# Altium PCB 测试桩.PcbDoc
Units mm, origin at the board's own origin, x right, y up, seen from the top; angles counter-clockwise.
Board outline 97.4 x 53.11 mm, 4 copper layers (Top Layer, Internal Plane 1, Internal Plane 2, Bottom Layer); 73 components, 53 nets, 362 pads, 111 vias.
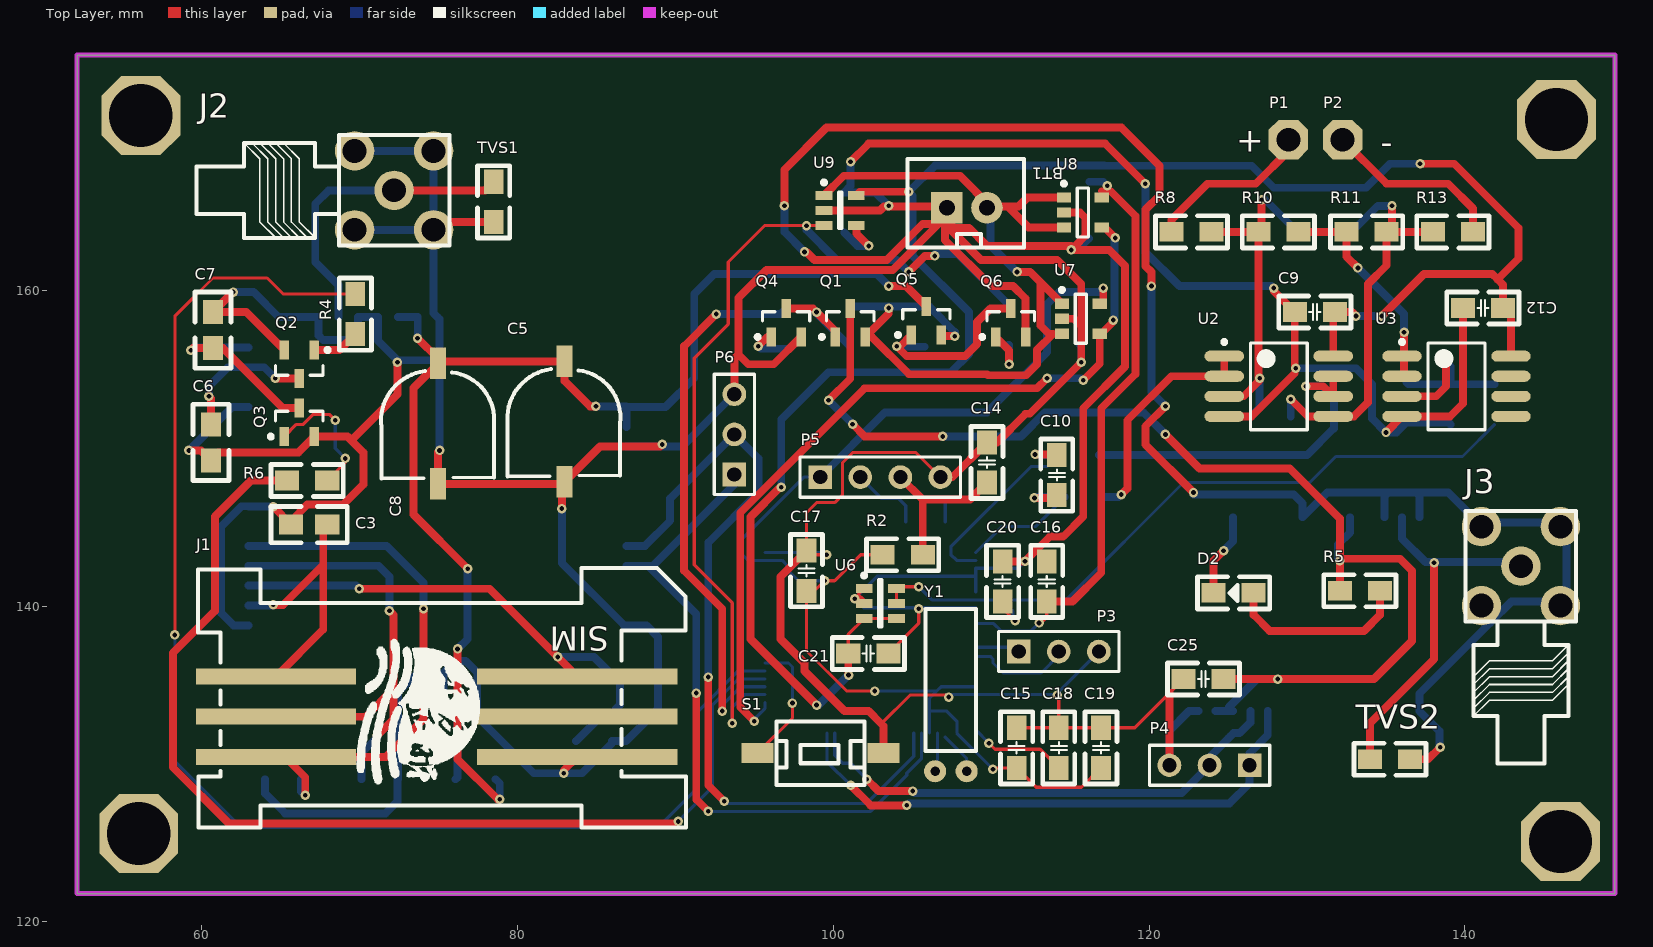
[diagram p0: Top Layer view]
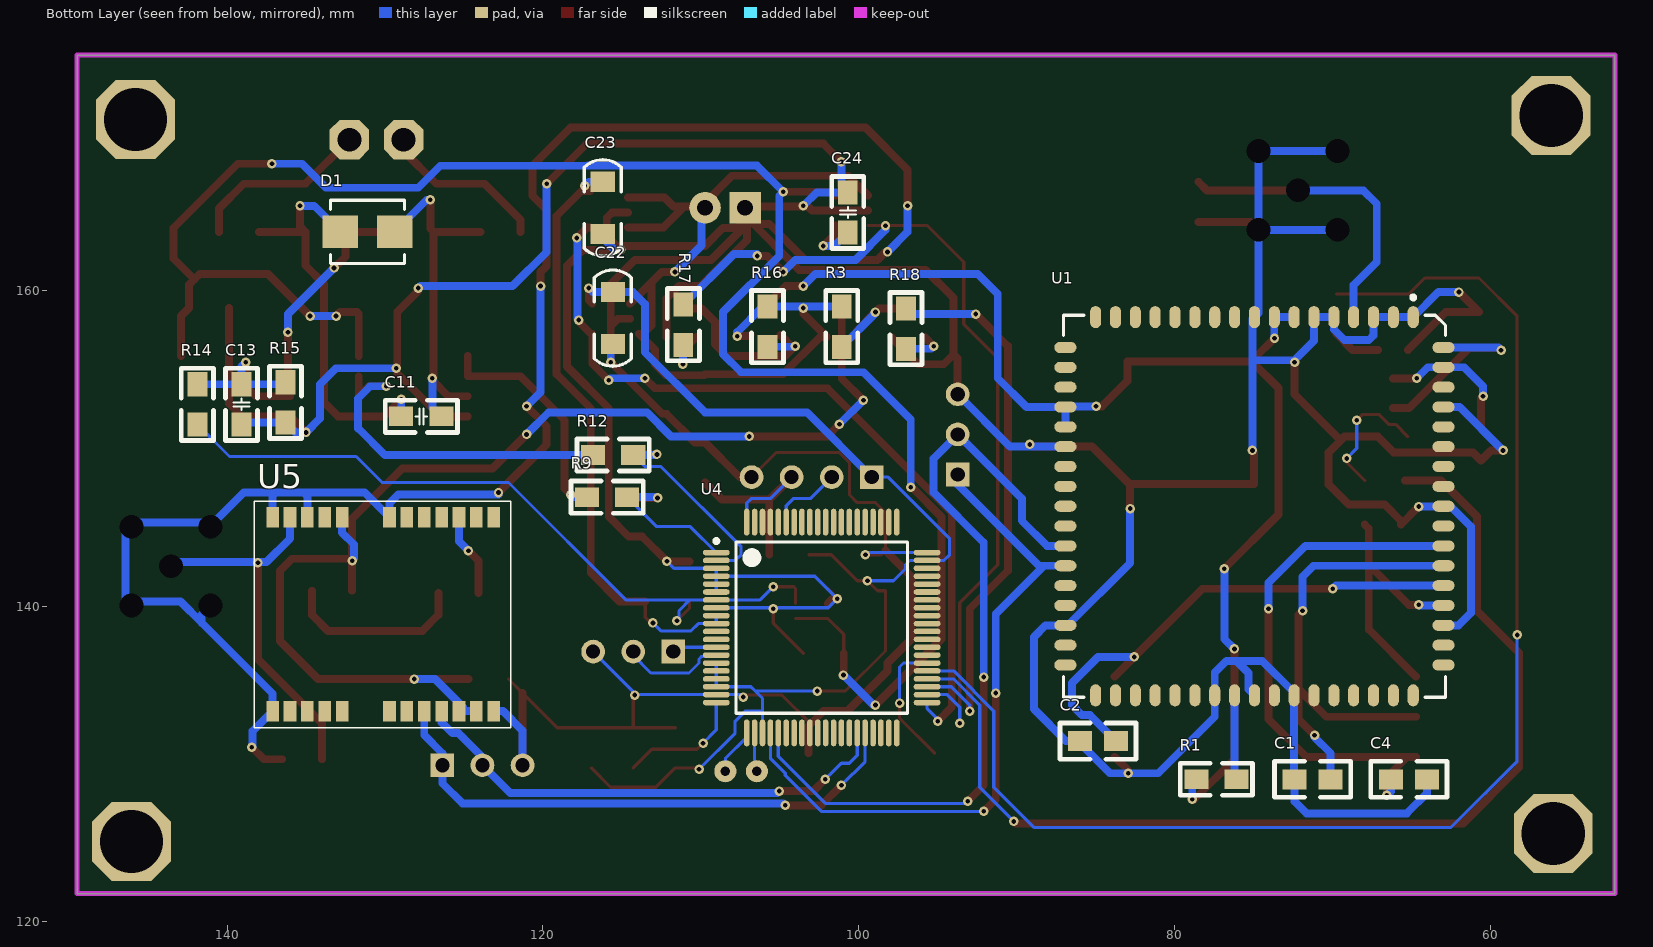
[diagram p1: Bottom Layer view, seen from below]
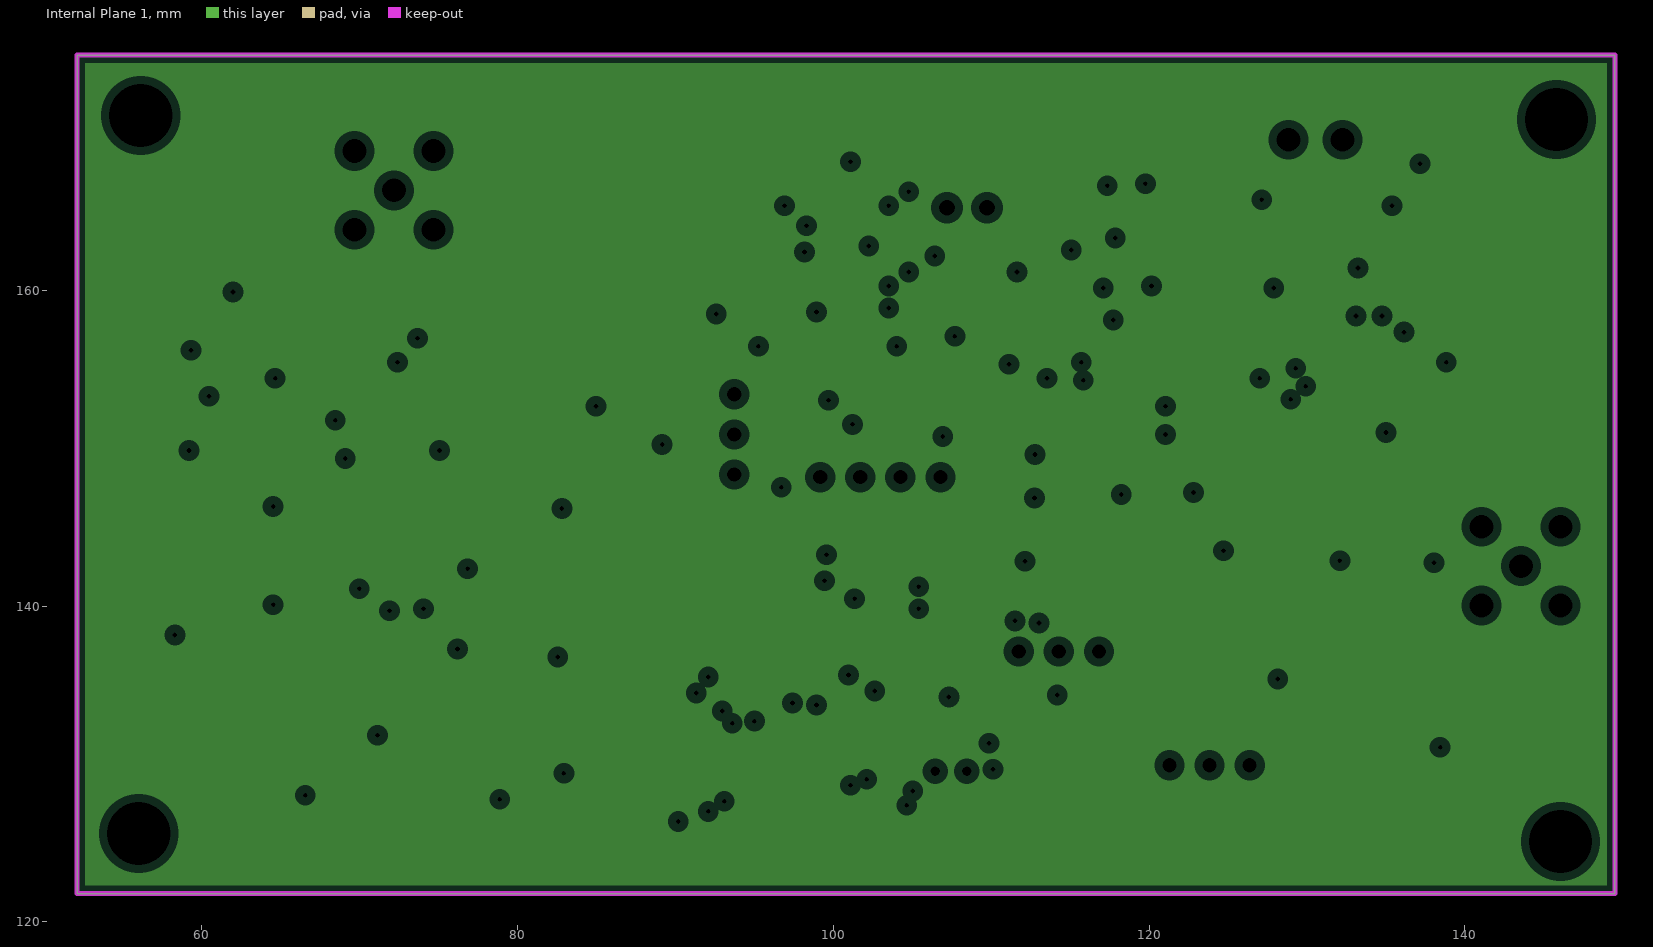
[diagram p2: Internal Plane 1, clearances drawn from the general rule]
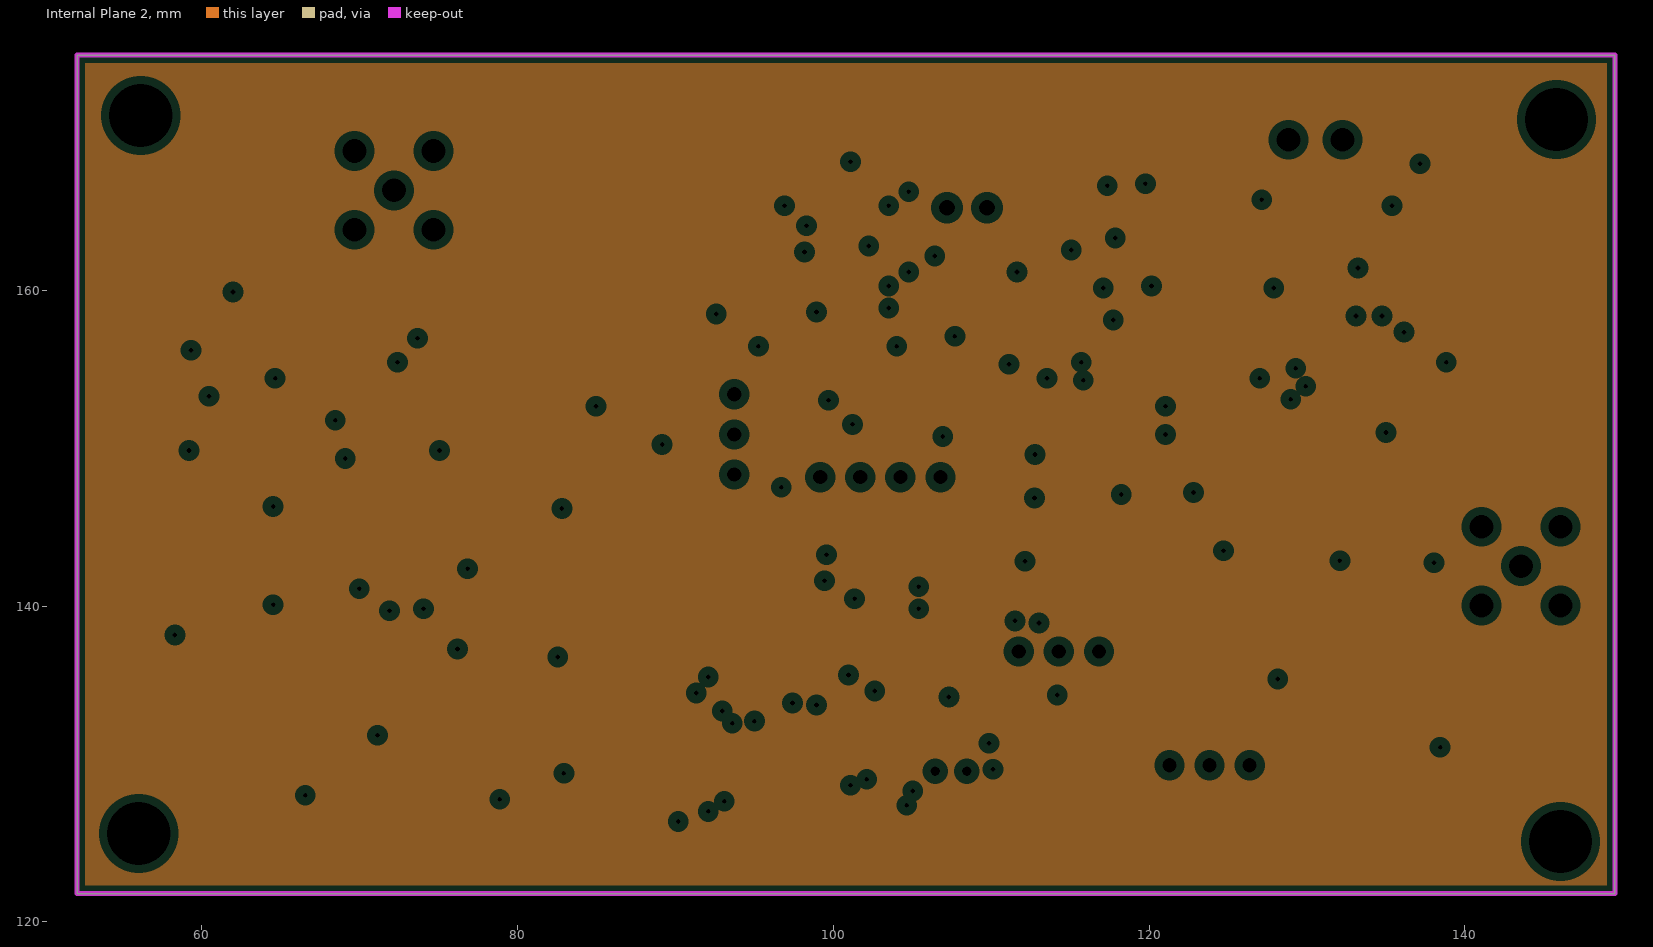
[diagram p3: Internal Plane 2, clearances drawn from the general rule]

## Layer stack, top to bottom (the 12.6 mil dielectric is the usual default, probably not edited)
Top Layer: signal copper 0.0356
Dielectric: dielectric 0.32, FR-4, Dk 4.8
Internal Plane 1: plane copper 0.0356
Dielectric: dielectric 0.32, FR-4, Dk 4.8
Internal Plane 2: plane copper 0.0356
Dielectric: dielectric 0.32, FR-4, Dk 4.8
Bottom Layer: signal copper 0.0356

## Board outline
52.1,121.793 52.1,174.9 149.5,174.9 149.5,121.793

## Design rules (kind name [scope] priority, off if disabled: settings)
Clearance Ploygon_Clearance [InPolygon] p1: gap=0.5
Clearance [All] p2: gap=0.15
PlaneClearance [All] p1: clearance=0.508
PlaneConnect [All] p1: planeconnectstyle=Relief reliefexpansion=0.508 reliefentries=4 reliefconductorwidth=0.254 reliefairgap=0.254
PolygonConnect [All] p1: connectstyle=Relief reliefconductorwidth=0.254 reliefentries=4 polygonreliefangle="90 Angle" airgapwidth=0.254
RoutingVias [All] p1: holewidth=0.3 width=0.6 viastyle="Through Hole" minholewidth=0.3 minwidth=0.6 maxholewidth=0.3 maxwidth=0.6
SolderMaskExpansion [All] p1: expansion=0.102
Width [All] p1: maxlimit=2 minlimit=0.2 preferedwidth=0.2 minimp=50.000000 maximp=50.000000 favimp=50.000000
26 further rules are at their usual default settings.

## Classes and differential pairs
component class U_GPRS模块: C1 C2 C3 C4 C5 C6 C7 C8 J1 J2 Q2 Q3 R1 R4 R6 TVS1 U1
component class U_GPS模块: C25 D2 J3 R5 TVS2 U5
component class U_信号调理: C9 C10 C11 C12 C13 D1 P1 P2 R8 R9 R10 R11 R12 R13 R14 R15 U2 U3
component class U_核心板: C14 C15 C16 C17 C18 C19 C20 C21 P3 P4 P5 P6 R2 S1 U4 U6 Y1
component class U_电源管理: BT1 C22 C23 C24 Q1 Q4 Q5 Q6 R3 R16 R17 R18 U7 U8 U9

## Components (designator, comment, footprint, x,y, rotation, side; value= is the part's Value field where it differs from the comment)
BT1 "" XH2.54-2P 107.188,165.227 r0 top
C1 "Cap" 0805 70.104,129.032 r0 bottom
C2 "Cap" 0805 83.693,131.445 r0 bottom
C3 "Cap" 0805 67.945,145.161 r180 top
C4 "Cap" 0805 66.294,129.032 r180 bottom
C5 "16V" 铝电解电容 82.931,155.067 r270 top
C6 "Cap" 0805 60.579,151.511 r270 top
C7 "Cap" 0805 60.706,156.337 r90 top
C8 "16V" 铝电解电容 74.93,154.94 r270 top
C9 "" 0805C 131.765,158.623 r180 top
C10 "Cap" 0805C 114.15,147.026 r90 top
C11 "" 0805C 128.971,152.019 r180 bottom
C12 "" 0805C 142.411,158.877 r180 top
C13 "" 0805C 139.087,151.511 r90 bottom
C14 "" 0805C 109.728,150.368 r270 top
C15 "" 0805C 111.61,129.754 r90 top
C16 "" 0805C 113.515,140.295 r90 top
C17 "" 0805C 98.298,140.97 r90 top
C18 "" 0805C 114.277,129.754 r90 top
C19 "" 0805C 116.944,129.754 r90 top
C20 "" 0805C 110.721,142.835 r270 top
C21 "" 0805C 103.482,136.993 r180 top
C22 "" 1206C 115.57,159.893 r270 bottom
C23 "" 1206C 116.205,166.878 r270 bottom
C24 "" 0805C 100.688,166.203 r270 bottom
C25 "Cap" 0805C 124.714,135.382 r180 top
D1 "SMCJ6.5CA" DO-214AA 131.108,163.703 r180 bottom
D2 "" 0805D 125.349,140.843 r180 top
J1 "SIM" SIM-6 72.898,134.239 r180 top
J2 "*" SM_ANT 74.676,163.83 r180 top
J3 "Antenna" SM_ANT 146.05,145.034 r270 top
P1 "Plug" PZ1 128.822,169.545 r180 top
P2 "Plug" PZ1 132.251,169.545 r180 top
P3 "Header 3" HDR1X3 111.737,137.12 r0 top
P4 "Header 3" HDR1X3 126.365,129.921 r180 top
P5 "Header 4" HDR1X4 99.164,148.169 r0 top
P6 "Header 3" HDR1X3 93.726,148.336 r90 top
Q1 "IRLML6401TRPBF" SOT23-3 101.069,157.948 r90 top
Q2 "NPN" SOT23-3 66.167,155.321 r270 top
Q3 "NPN" SOT23-3 66.167,151.638 r90 top
Q4 "8050" SOT23-3 97.005,157.948 r90 top
Q5 "IRLML6401TRPBF" SOT23-3 105.895,158.075 r90 top
Q6 "8050" SOT23-3 111.229,157.948 r90 top
R1 "Res2" 0805r 76.073,129.032 r0 bottom
R2 "" 0805R 103.124,143.256 r0 top
R3 "" 0805R 101.069,158.964 r270 bottom
R4 "Res2" 0805r 69.723,159.766 r270 top
R5 "Res2" 0805R 134.62,140.97 r180 top
R6 "Res2" 0805r 65.405,147.955 r0 top
R8 "" 0805R 121.412,163.703 r0 top
R9 "" 0805R 117.198,146.899 r180 bottom
R10 "" 0805R 126.917,163.703 r0 top
R11 "" 0805R 132.505,163.703 r0 top
R12 "" 0805R 116.817,149.566 r180 bottom
R13 "" 0805R 137.966,163.703 r0 top
R14 "" 0805R 141.881,151.511 r90 bottom
R15 "" 0805R 136.293,154.178 r270 bottom
R16 "" 0805R 105.768,158.964 r270 bottom
R17 "" 0805R 111.102,159.091 r270 bottom
R18 "" 0805R 97.005,158.837 r270 bottom
S1 "SW-PB" SW-KEY 99.187,130.683 r0 top
TVS1 "Res2" 0805r 78.486,164.338 r90 top
TVS2 "Res2" 0805r 136.525,130.302 r180 top
U1 "MG323-B" MG323-b 74.93,146.327 r270 bottom
U2 "OPA2335" SOP-8 128.209,153.924 r0 top
U3 "LM358" SOP-8 139.468,153.924 r0 top
U4 "MSP430F6720IPNR" QFP-80 102.339,138.644 r180 bottom
U5 "NEO-7M-0-000" NEO-7 132.715,133.35 r270 bottom
U6 "REF3212" SOT23-6 102.974,140.168 r0 top
U7 "TPS780330220" SOT23-5 115.674,158.202 r0 top
U8 "TPS780330220" SOT23-5 115.801,164.933 r0 top
U9 "TPS71733DCKR" SC70-5 100.434,165.06 r0 top
Y1 "XTAL" XTAL2 107.442,129.54 r0 top

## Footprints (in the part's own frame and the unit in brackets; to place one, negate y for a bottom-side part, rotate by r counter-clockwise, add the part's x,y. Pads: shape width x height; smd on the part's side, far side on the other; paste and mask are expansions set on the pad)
0805 [mil]
  rect 60x50 smd: 1(0,0) 2(90,0)
  silkscreen extent -50,-45 140,45
0805C [mm]
  rect 1.524x1.25 smd: 1(0,0) 2(2.54,0)
  silkscreen extent -1.02,-1.02 3.56,1.02
0805D [mm]
  rect 1.524x1.25 smd: 1(-1.27,0) 2(1.27,0)
  silkscreen extent -2.29,-1.02 2.29,1.02
0805r [mm]
  rect 1.524x1.25 smd: 1(0,0) 2(2.54,0)
  silkscreen extent -1.02,-1.02 3.56,1.02
0805R [mm]
  rect 1.524x1.25 smd: 1(0,0) 2(2.54,0)
  silkscreen extent -1.02,-1.02 3.56,1.02
1206C [mil]
  rect 50x60 smd: 1(0,0) 2(130,0)
  silkscreen extent -55,-46 185,46
DO-214AA [mm] "DO-214AA"
  rect 2.25x2.05 smd: 1(-1.725,0) 2(1.725,0)
  silkscreen extent -2.35,-2 2.35,2, body extent -2.35,-1.97 2.35,1.97, height 2.44
HDR1X3 [mm] "Connector; Header; 3 Position"
  rect 1.5x1.5 hole 0.9: 1(0,0)
  round 1.5 hole 0.9: 2(2.54,0) 3(5.08,0)
  silkscreen extent -1.27,-1.27 6.35,1.27
HDR1X4 [mm] "Connector; Header; 4 Position"
  rect 1.5x1.5 hole 0.9: 1(0,0)
  round 1.5 hole 0.9: 2(2.54,0) 3(5.08,0) 4(7.62,0)
  silkscreen extent -1.27,-1.27 8.89,1.27
MG323-b [mm] "LCC, 68-Pins, Body 24.2x24.2mm (max), Pitch 1.26mm, IPC Medium Density"
  oval 1.4x0.7 smd: 1(-11.975,10.056) 2(-11.975,8.799) 3(-11.975,7.542) 4(-11.975,6.285) 5(-11.975,5.028) 6(-11.975,3.771) 7(-11.975,2.514) 8(-11.975,1.257) 9(-11.975,0) 10(-11.975,-1.257) 11(-11.975,-2.514) 12(-11.975,-3.771) 13(-11.975,-5.028) 14(-11.975,-6.285) 15(-11.975,-7.542) 16(-11.975,-8.799) 17(-11.975,-10.056) 35(11.975,-10.056) 36(11.975,-8.799) 37(11.975,-7.542) 38(11.975,-6.285) 39(11.975,-5.028) 40(11.975,-3.771) 41(11.975,-2.514) 42(11.975,-1.257) 43(11.975,0) 44(11.975,1.257) 45(11.975,2.514) 46(11.975,3.771) 47(11.975,5.028) 48(11.975,6.285) 49(11.975,7.542) 50(11.975,8.799) 51(11.975,10.056)
  oval 0.7x1.4 smd: 18(-10.056,-11.975) 19(-8.799,-11.975) 20(-7.542,-11.975) 21(-6.285,-11.975) 22(-5.028,-11.975) 23(-3.771,-11.975) 24(-2.514,-11.975) 25(-1.257,-11.975) 26(0,-11.975) 27(1.257,-11.975) 28(2.514,-11.975) 29(3.771,-11.975) 30(5.028,-11.975) 31(6.285,-11.975) 32(7.542,-11.975) 33(8.799,-11.975) 34(10.056,-11.975) 52(10.056,11.975) 53(8.799,11.975) 54(7.542,11.975) 55(6.285,11.975) 56(5.028,11.975) 57(3.771,11.975) 58(2.514,11.975) 59(1.257,11.975) 60(0,11.975) 61(-1.257,11.975) 62(-2.514,11.975) 63(-3.771,11.975) 64(-5.028,11.975) 65(-6.285,11.975) 66(-7.542,11.975) 67(-8.799,11.975) 68(-10.056,11.975)
  silkscreen extent -13.35,-12.1 12.1,12.1, body extent -12.13,-12.13 11.87,11.87, height 3.02
NEO-7 [mm] "GPS模块"
  rect 1.3x0.8 smd: 1(-12.28,9.6) 2(-12.28,8.5) 3(-12.28,7.4) 4(-12.28,6.3) 5(-12.28,5.2) 6(-12.28,4.1) 7(-12.28,3) 8(-12.28,0) 8(-12.28,0) 9(-12.28,-1.1) 10(-12.28,-2.2) 11(-12.28,-3.3) 12(-12.28,-4.4) 13(0,-4.4) 13(0,-4.4) 14(0,-3.3) 15(0,-2.2) 16(0,-1.1) 17(0,0) 18(0,3) 19(0,4.1) 20(0,5.2) 21(0,6.3) 22(0,7.4) 23(0,8.5) 24(0,9.6)
  silkscreen extent -13.3,-5.56 1.04,10.67
PZ1 [mm]
  oct 2.5x2.5 hole 1.5: 1(0,0)
QFP-80 [mm]
  oval 1.7x0.35 smd: 1(-6.675,4.75) 2(-6.675,4.25) 3(-6.675,3.75) 4(-6.675,3.25) 5(-6.675,2.75) 6(-6.675,2.25) 7(-6.675,1.75) 8(-6.675,1.25) 9(-6.675,0.75) 10(-6.675,0.25) 11(-6.675,-0.25) 12(-6.675,-0.75) 13(-6.675,-1.25) 14(-6.675,-1.75) 15(-6.675,-2.25) 16(-6.675,-2.75) 17(-6.675,-3.25) 18(-6.675,-3.75) 19(-6.675,-4.25) 20(-6.675,-4.75) 41(6.675,-4.75) 42(6.675,-4.25) 43(6.675,-3.75) 44(6.675,-3.25) 45(6.675,-2.75) 46(6.675,-2.25) 47(6.675,-1.75) 48(6.675,-1.25) 49(6.675,-0.75) 50(6.675,-0.25) 51(6.675,0.25) 52(6.675,0.75) 53(6.675,1.25) 54(6.675,1.75) 55(6.675,2.25) 56(6.675,2.75) 57(6.675,3.25) 58(6.675,3.75) 59(6.675,4.25) 60(6.675,4.75)
  oval 0.35x1.7 smd: 21(-4.75,-6.675) 22(-4.25,-6.675) 23(-3.75,-6.675) 24(-3.25,-6.675) 25(-2.75,-6.675) 26(-2.25,-6.675) 27(-1.75,-6.675) 28(-1.25,-6.675) 29(-0.75,-6.675) 30(-0.25,-6.675) 31(0.25,-6.675) 32(0.75,-6.675) 33(1.25,-6.675) 34(1.75,-6.675) 35(2.25,-6.675) 36(2.75,-6.675) 37(3.25,-6.675) 38(3.75,-6.675) 39(4.25,-6.675) 40(4.75,-6.675) 61(4.75,6.675) 62(4.25,6.675) 63(3.75,6.675) 64(3.25,6.675) 65(2.75,6.675) 66(2.25,6.675) 67(1.75,6.675) 68(1.25,6.675) 69(0.75,6.675) 70(0.25,6.675) 71(-0.25,6.675) 72(-0.75,6.675) 73(-1.25,6.675) 74(-1.75,6.675) 75(-2.25,6.675) 76(-2.75,6.675) 77(-3.25,6.675) 78(-3.75,6.675) 79(-4.25,6.675) 80(-4.75,6.675)
  silkscreen extent -6.8,-5.43 5.43,5.6, body extent -4.75,-4.75 4.75,4.75, height 2.45
SC70-5 [mm] "SOT23, 5-Leads, Body 2.03x2.45mm, Pitch 0.95mm, IPC Medium Density"
  rect 1.05x0.55 smd: 1(-1.025,0.95) 2(-1.025,0) 3(-1.025,-0.95) 4(1.025,-0.95) 5(1.025,0.95)
  silkscreen extent -1.15,-1.15 0.1,1.9, body extent -0.67,-1.12 0.67,1.13, height 1.1
SIM-6 [mil]
  rect 400x40 smd: 1(322.79,149) 2(322.79,49) 3(322.79,-51)
  rect 500x40 smd: 4(-428.78,-51) 5(-428.78,49) 6(-428.78,149)
  silkscreen extent -700,-322 518,326, body extent -676,-341 490,336, height 102
SM_ANT [mm]
  round 2.5 / inner round 0 / far side round 0 hole 1.5: 1(2.5,-2.5) 2(0,0) 2(0,-5) 2(5,0) 2(5,-5)
  silkscreen extent -1,-6 15,1, body extent -1.07,-6.1 14.03,0.9, height 9.86
SOP-8 [mm]
  oval 2.5x0.7 smd: 1(-3.45,1.905) 2(-3.45,0.635) 3(-3.45,-0.635) 4(-3.45,-1.905) 5(3.45,-1.905) 6(3.45,-0.635) 7(3.45,0.635) 8(3.45,1.905)
  silkscreen extent -3.57,-2.75 1.8,2.93, body extent -2.73,-2.75 2.73,2.75, height 2.03
SOT23-3 [mm] "SOT23, 3-Leads, Body 2.9x1.3mm, Pitch 0.95mm, Lead Span 2.5mm, IPC High Density"
  rect 1.2x0.6 smd: 1(-0.9,0.95) 2(-0.9,-0.95) 3(0.9,0)
  silkscreen extent -1.02,-1.5 0.7,1.92, body extent -0.7,-1.5 0.7,1.5, height 1.1
SOT23-5 [mm] "SOT23, 5-Leads, Body 2.9x1.6mm, Pitch 0.95mm, Lead Span 2.8mm, IPC High Density"
  rect 0.9x0.65 smd: 1(-1.2,0.95) 2(-1.2,0) 3(-1.2,-0.95) 4(1.2,-0.95) 5(1.2,0.95)
  silkscreen extent -1.32,-1.55 0.35,1.95, body extent -0.9,-1.55 0.9,1.55, height 1.45
SOT23-6 [mm] "SOT23, 6-Leads, Body 2.90x2.45mm, Pitch 0.95mm, IPC Medium Density"
  rect 1.05x0.55 smd: 1(-1.025,0.95) 2(-1.025,0) 3(-1.025,-0.95) 4(1.025,-0.95) 5(1.025,0) 6(1.025,0.95)
  silkscreen extent -1.15,-1.5 0.1,1.9, body extent -1.4,-1.45 1.4,1.45, height 1.45
SW-KEY [mm]
  rect 2.032x1.27 smd: 1(-4,0) 2(4,0)
  silkscreen extent -2.8,-2 2.8,2
XH2.54-2P [mm] "脚间距2.54的防呆插座"
  rect 2x2 hole 1: 1(0,0)
  round 2 hole 1: 2(2.54,0)
  silkscreen extent -2.5,-2.5 4.9,3.1
XTAL2 [mm] "3.2 X 9"
  round 1.4 hole 0.6: 1(-1,0) 2(1,0)
  silkscreen extent -1.6,1.27 1.6,10.27
铝电解电容 [mm]
  rect 2x1 smd: 1(-0.43,0.037) 2(7.199,0.037)
  silkscreen extent 0.06,-3.59 6.84,3.59

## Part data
BT1: library part "Header 2", "Header, 2-Pin"
C1 C2 C3 C4 C6 C7: "Capacitor"
C5 C8: library part "Cap Pol2", "贴片铝电解电容"
C9 C11 C12 C13 C20 C21 C24: library part Cap, "瓷片电容"
C10 C25: "贴片电容"
C14 C15 C16 C17 C18 C19: library part Cap, "贴片电容"
C22 C23: library part "Cap Pol1", "钽电容"
D1: library part DIODE_TVS, "双向TVS二极管 5V耐压"
D2: library part LED2, "贴片红色发光管"
J1: library part CON6, "Connector"
J2: library part C, "Connector"
J3: "天线"
P3 P4 P6: "Header, 3-Pin"
P5: "Header, 4-Pin"
Q1 Q5: "小功率MOSFET"
Q2 Q3 Q4 Q6: library part NPN_SOT, "NPN型贴片三极管"
R1 R4 R6 TVS1 TVS2: "Resistor"
R2 R8 R9 R10 R11 R12 R13 R14 R15: library part Res2, "贴片电阻"
R3 R16 R17 R18: library part Res2, "碳膜电阻"
R5: "贴片碳膜电阻"
S1: "Switch"
U2: "自归零CMOS运放"
U3: "运算放大器"
U4: library part MSP430F6720, "MSP430处理器80引脚封装"
U5: library part NEO-7, "U-Blox GPRS模块"
U6: "串联基准"
U7 U8: library part TPS780220330, "线性稳压器"
U9: library part TPS71701, "高PSRR线性稳压器"
Y1: "无源晶振"

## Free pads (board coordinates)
  oct 5x5 hole 4: 0(56.007,125.603) 0(56.134,171.069) 0(145.796,170.815) 0(146.05,125.095)

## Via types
v1: diameter 0.6, hole 0.3, Top Layer to Bottom Layer, 111 vias

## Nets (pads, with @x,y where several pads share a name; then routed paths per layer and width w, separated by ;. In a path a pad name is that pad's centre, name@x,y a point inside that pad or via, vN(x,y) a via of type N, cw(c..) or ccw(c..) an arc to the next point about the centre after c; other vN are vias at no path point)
+1.25V: C20.2 R14.1 U4.7 U6.5 U6.6 | length 47
  Top Layer w0.2: U6.5 U6.6 104.104,141.224 v1(105.41,141.224) ; C20.2 110.721,139.85 v1(111.506,139.065)
  Bottom Layer w0.2: v1(105.41,141.224) 106.24,140.394 U4.7 110.685,140.394 ; v1(111.506,139.065) 111.379,139.192 111.379,139.7 110.685,140.394 ; R14.1 139.849,149.479 131.826,149.479 130.175,147.828 122.174,147.828 114.74,140.394 110.685,140.394
ANALOG_OUTPUT_N: C10.2 R12.2 U4.2 | length 14.4
  Top Layer w0.5: v1(112.776,149.606) 114.11,149.606 C10.2
  Bottom Layer w0.2: U4.2 107.804,142.894 107.442,143.256 107.442,143.764 112.522,148.844 113.554,148.844 R12.2
  Bottom Layer w0.5: v1(112.776,149.606) 112.816,149.566 R12.2
ANALOG_OUTPUT_P: C10.1 R9.2 U4.1 | length 10.6
  Top Layer w0.5: v1(112.736,146.852) 113.975,146.852 C10.1
  Bottom Layer w0.2: U4.1 110.653,145.034 112.792,145.034 R9.2
  Bottom Layer w0.5: v1(112.736,146.852) 112.736,146.899 R9.2
ANALOG_POWER: C9.1 C12.1 C21.2 U2.8 U3.8 U6.3 U6.4 U9.5 | length 124
  Top Layer w0.2: C21.2 100.942,138.211 U6.3 U6.4
  Top Layer w0.5: v1(96.697,147.524) 96.627,147.524 94.749,145.646 94.749,137.915 v1(98.933,133.731) ; C21.2 100.942,135.659 v1(100.965,135.636) ; U9.5 101.691,166.243 v1(104.775,166.243) ; U2.8 C9.1@131.659,158.517 ; C9.1 132.857,158.623 133.096,158.384 v1(133.096,158.369) ; v1(134.747,158.369) 137.414,161.036 141.732,161.036 142.071,160.697 ; v1(137.16,168.021) 139.319,168.021 143.383,163.957 143.383,162.008 142.071,160.697 ; U3.8 142.918,158.37 C12.1 142.411,160.357 142.071,160.697
  Bottom Layer w0.5: v1(96.697,147.524) 96.697,151.815 99.695,154.813 107.442,154.813 108.585,155.956 108.585,158.623 105.029,162.179 105.029,165.989 v1(104.775,166.243) 106.445,167.913 117.133,167.913 117.152,167.894 126.492,167.894 127.889,166.497 133.731,166.497 135.255,168.021 v1(137.16,168.021) ; v1(98.933,133.731) 99.06,133.731 v1(100.965,135.636) ; v1(133.096,158.369) v1(134.747,158.369)
AVCC: C16.1 C23.1 U4.9 U4.10 U8.5 | length 38.3
  Top Layer w0.2: v1(113.03,138.938) 113.157,138.938 113.515,139.296 C16.1
  Top Layer w0.5: C16.1 115.149,140.295 116.967,142.113 116.967,152.527 119.126,154.686 119.126,164.719 117.568,166.277 117.001,166.277
  Bottom Layer w0.2: U4.9 U4.10 110.153,138.894 110.617,138.43 112.522,138.43 v1(113.03,138.938)
  Bottom Layer w0.5: C23.1 117.094,166.878 v1(117.348,166.624)
DVCC: C15.1 C17.1 C19.1 C22.1 P5.1 R2.1 U4.15 U4.16 U4.17 U4.18 U4.23 U4.59 U7.5 | length 79.1
  Top Layer w0.2: v1(102.616,134.62) 100.838,134.62 98.298,137.16 C17.1 98.806,140.97 v1(99.441,141.605) 100.076,141.605 101.727,143.256 R2.1 ; v1(110.109,129.667) 110.196,129.754 C15.1 112.84,128.524 115.713,128.524 C19.1
  Top Layer w0.5: U7.5 117.094,159.373 v1(117.094,160.147)
  Bottom Layer w0.2: P5.1 98.131,148.169 94.234,144.272 94.234,143.256 94.596,142.894 U4.59 96.755,142.894 97.028,142.621 97.028,142.367 97.79,141.605 v1(99.441,141.605) ; v1(102.616,134.62) 106.553,134.62 ; U4.23 106.089,133.35 ; U4.15 U4.16 U4.17 U4.18 106.827,134.894 106.553,134.62 ; v1(110.109,129.667) 107.823,131.953 107.823,132.715 107.188,133.35 106.089,133.35 ; 106.089,133.35 106.089,134.156 106.553,134.62
  Bottom Layer w0.5: P5.1 103.267,152.273 109.728,152.273 113.538,156.083 113.538,159.131 114.3,159.893 C22.1 116.84,159.893 v1(117.094,160.147)
GND: BT1.1 C1.2 C2.2 C3.2 C4.2 C5.2 C6.2 C7.2 C8.2 C9.2 C12.2 C13.1 C14.1 C15.2 C16.2 C17.2 C18.2 C19.2 C20.1 C21.1 C22.2 C23.2 C24.1 C25.2 J1.6 J2.2 J3.2 P3.3 P4.3 P5.4 P6.3 Q2.2 Q3.2 Q4.2 Q6.2 R15.2 S1.2 TVS1.1 TVS2.1 U1.1 U1.2 U1.3 U1.5 U1.6 U1.9 U1.23 U1.32 U1.41 U1.43 U1.45 U1.54 U1.60 U1.65 U2.4 U3.4 U4.3 U4.4 U4.5 U4.6 U4.8 U4.19 U4.60 U5.7 U5.10 U5.12 U5.13 U5.24 U6.1 U6.2 U7.2 U8.2 U9.2 | length 602.4
  Top Layer w0.2: v1(99.568,143.256) 98.552,143.256 C17.2 98.298,145.923 98.933,146.558 100.076,146.558 100.584,147.066 100.584,149.098 101.219,149.733 105.22,149.733 P5.4 ; v1(101.346,140.462) 101.346,140.516 U6.1 ; 103.037,132.548 104.854,134.366 107.188,134.366 v1(107.315,134.239) ; C21.1 105.41,138.922 v1(105.41,139.827) ; C15.2 C18.2 ; v1(114.173,134.366) 114.277,134.262 C18.2 ; C25.2 121.285,134.493 119.086,132.294 C19.2 C18.2
  Top Layer w0.5: v1(59.182,149.86) 59.944,149.86 C6.2 61.087,149.733 66.112,149.733 Q3.2 69.226,150.738 69.469,150.495 ; v1(61.976,159.893) C7.2 62.815,158.623 Q2.2 ; v1(64.516,146.304) C3.2 65.659,145.415 66.675,146.431 68.961,146.431 70.231,147.701 70.231,149.733 69.469,150.495 ; v1(72.39,155.448) 72.39,153.416 69.469,150.495 ; J2.2@74.676,163.83 75.184,164.338 TVS1.1 ; v1(75.057,149.86) 74.967,149.77 C8.2 C5.2@82.841,147.741 ; v1(82.804,146.177) 82.804,147.704 C5.2@82.841,147.741 ; v1(82.931,129.413) 82.931,129.596 J1.6 ; v1(89.154,150.241) 89.027,150.114 85.214,150.114 C5.2 C5.2@82.841,147.741 ; P6.3 93.726,155.702 93.98,155.956 ; v1(96.901,165.354) 96.901,167.64 99.568,170.307 118.237,170.307 120.65,167.894 120.65,165.989 119.776,165.115 119.776,161.529 120.142,161.163 v1(120.142,160.274) ; Q4.2 96.227,155.321 94.615,155.321 93.98,155.956 ; v1(98.171,162.433) 98.298,162.433 98.806,161.925 103.378,161.925 105.664,164.211 106.315,164.211 BT1.1@107.061,164.957 ; C17.2 96.647,141.859 96.647,137.922 98.171,136.398 98.171,135.89 100.711,133.35 102.235,133.35 103.037,132.548 103.187,132.398 S1.2 ; U9.2 102.957,165.06 103.211,165.314 BT1.1@106.664,165.314 ; v1(101.092,168.148) 102.235,169.291 117.221,169.291 v1(119.761,166.751) ; v1(101.346,140.462) 101.655,140.462 U6.2 ; P5.4 107.529,148.169 C14.1 110.363,150.368 112.179,152.184 112.433,152.184 v1(115.697,155.448) 115.697,157.734 ; BT1.1@107.419,164.592 BT1.1@107.419,164.234 ; BT1.1@107.419,165.314 BT1.1@107.061,164.957 ; C20.1 v1(112.141,142.835) 113.705,144.399 114.554,144.399 115.824,145.669 115.824,152.527 118.476,155.179 118.476,161.559 117.475,162.56 v1(115.062,162.56) ; Q6.2 112.179,159.474 111.379,160.274 109.982,160.274 107.061,163.195 BT1.1@107.061,164.592 ; U7.2 115.229,158.202 115.697,157.734 ; U8.2 115.61,164.933 115.951,164.592 115.951,163.449 115.316,162.814 ; v1@115.062,162.814 109.728,162.814 108.585,163.957 107.696,163.957 BT1.1@107.419,164.234 ; v1(121.031,152.654) 119.761,151.384 119.761,150.241 v1(122.809,147.193) ; P4.3 121.285,134.493 ; U2.4 126.492,152.019 129.225,154.752 ; v1(127.889,160.147) 127.889,159.959 C9.2 v1@129.225,155.067 ; v1(135.001,151.003) U3.4 139.065,152.019 139.871,152.825 C12.2 ; TVS2.1 137.668,130.302 v1(138.43,131.064) ; 93.98,155.956 93.98,159.512 95.758,161.29 103.759,161.29 BT1.1@107.061,164.592 ; BT1.1@107.061,164.592 BT1.1@107.061,164.957 ; BT1.1@107.419,164.234 107.419,163.853 109.347,161.925 114.173,161.925 115.697,160.401 115.697,157.734
  Bottom Layer w0.2: U4.60 99.43,143.394 v1(99.568,143.256) ; v1(107.315,134.239) 107.47,134.394 U4.19 v1@114.091,134.394 ; U4.8 101.914,139.894 v1(101.346,140.462) 102.778,141.894 U4.4 ; U4.6 U4.5 U4.4 ; v1(112.141,142.835) 111.7,142.394 U4.3 U4.4 ; v1@114.118,134.421 P3.3
  Bottom Layer w0.5: v1(59.182,149.86) 61.934,152.612 U1.65 ; v1(61.976,159.893) 63.283,159.893 U1.1 U1.2 U1.3 67.388,157.148 67.691,156.845 69.215,156.845 69.902,157.532 U1.5 U1.6 71.159,156.806 v1@72.39,155.575 ; U1.54 62.002,138.785 61.214,139.573 61.214,145.034 62.507,146.327 U1.60 62.978,146.304 v1(64.516,146.304) ; C4.2 64.008,128.143 65.278,126.873 71.628,126.873 72.39,127.635 C1.2 72.416,129.058 U1.45 72.416,134.505 74.436,136.525 76.073,136.525 ; 69.676,163.83 74.676,163.83 ; 69.676,168.83 74.676,168.83 74.676,163.83 ; v1(72.39,155.448) v1@72.39,155.575 ; U1.43 75.311,134.733 75.311,135.763 76.073,136.525 ; v1(75.057,149.86) 75.057,155.575 ; v1(82.804,146.177) 82.804,142.732 86.751,138.785 U1.32 88.164,138.785 88.9,138.049 88.9,133.477 86.868,131.445 C2.2 85.979,131.318 84.074,129.413 v1(82.931,129.413) 81.026,129.413 77.444,132.995 U1.41 77.444,135.789 76.708,136.525 76.073,136.525 ; U1.23 90.408,150.098 P6.3 ; v1(96.901,165.354) 96.901,163.703 v1(98.171,162.433) ; v1(101.092,168.148) 101.092,166.608 C24.1 102.656,166.203 v1(103.505,165.354) ; v1(115.062,162.56) 115.459,162.56 C23.2@116.182,163.282 ; C22.2 115.697,156.464 v1(115.697,155.448) ; P3.3 P3.3@117.047,137.35 ; v1(119.761,166.751) 119.761,162.433 121.92,160.274 127.762,160.274 v1(127.889,160.147) ; v1(120.142,160.274) 120.142,153.543 v1(121.031,152.654) ; P4.3 121.285,132.109 122.526,133.35 U5.24 ; v1(122.809,147.193) 122.809,147.066 129.159,147.066 129.715,146.51 U5.7 131.278,147.193 135.128,147.193 ; v1(129.286,155.067) 133.096,155.067 134.112,154.051 134.112,151.892 v1(135.001,151.003) 135.658,151.003 R15.2 138.96,151.638 C13.1 ; U5.10 134.915,146.98 135.128,147.193 ; U5.12 137.115,146.984 136.906,147.193 ; v1(138.43,131.064) 138.385,131.109 138.385,132.08 137.115,133.35 137.115,134.448 141.605,138.938 ; 141.05,140.034 141.605,139.479 141.605,138.938 ; v1@72.39,155.575 75.057,155.575 ; 74.676,163.83 74.676,158.556 U1.9 75.057,158.175 75.057,155.575 ; 135.128,147.193 136.906,147.193 ; 136.906,147.193 138.946,147.193 141.141,144.998 141.431,145.288 146.431,145.288 146.431,140.288 142.955,140.288 141.605,138.938
GPRS_POWER: C5.1 C8.1 Q5.3 R1.2 U1.7 U1.8 U1.21 U1.22 | length 78.8
  Top Layer w0.5: v1(73.66,156.972) 74.967,155.665 C8.1 ; v1(76.2,137.287) 76.2,130.302 78.74,127.762 v1(78.867,127.762) ; v1(76.835,142.367) 73.406,145.796 73.406,153.809 C8.1 ; v1(84.963,152.654) 84.582,152.654 82.968,154.268 C5.1 75.094,155.497 C8.1 ; v1(103.505,160.274) 104.596,160.274 Q5.3
  Bottom Layer w0.5: U1.7 U1.8 73.673,156.985 v1(73.66,156.972) ; v1(76.2,137.287) 76.835,137.922 v1(76.835,142.367) ; R1.2 78.867,128.778 v1(78.867,127.762) ; v1(84.963,152.654) 86.863,152.654 U1.21 ; U1.22 U1.21 ; v1(103.505,160.274) 102.743,161.036 92.456,161.036 91.186,159.766 91.186,154.432 89.366,152.612 U1.21
GPRS_RXD: P6.1 U1.29 U4.24 | length 43.3
  Top Layer w0.5: v1(91.313,134.493) 91.313,127.762 v1(92.075,127)
  Bottom Layer w0.2: v1(92.075,127) 102.362,127 104.648,129.286 104.648,129.413 105.589,130.354 U4.24
  Bottom Layer w0.5: U1.29 88.265,142.556 ; v1(91.313,134.493) 91.313,139.508 88.265,142.556 ; P6.1 93.726,147.701 88.581,142.556 88.265,142.556
GPRS_TXD: P6.2 U1.28 U4.25 | length 50.9
  Top Layer w0.5: v1(92.075,135.509) 92.075,128.651 v1(93.091,127.635)
  Bottom Layer w0.2: v1(93.091,127.635) 93.218,127.508 102.108,127.508 105.089,130.489 U4.25
  Bottom Layer w0.5: U1.28 88.06,143.813 89.662,145.415 89.662,146.812 P6.2 95.25,149.352 95.25,147.193 92.075,144.018 v1(92.075,135.509)
GPS_POWER: C25.1 Q1.3 R5.2 U5.8 U5.22 U5.23 | length 78.1
  Top Layer w0.5: v1(99.695,153.035) 101.069,154.409 Q1.3 ; v1(101.219,151.511) 101.981,150.749 v1(106.934,150.749) ; v1(121.031,150.876) 123.19,148.717 128.905,148.717 132.08,145.542 v1(132.08,142.875) ; C25.1 v1(128.143,135.382) 134.239,135.382 136.652,137.795 136.652,142.24 135.89,143.002 132.207,143.002 v1(132.08,142.875) ; R5.2 v1(132.08,142.875)
  Bottom Layer w0.5: v1(99.695,153.035) v1(101.219,151.511) ; v1(106.934,150.749) 111.887,150.749 113.411,152.273 119.634,152.273 v1(121.031,150.876) ; U5.23 U5.22 ; U5.22@125.057,133.608 126.831,135.382 v1(128.143,135.382) ; v1(132.08,142.875) 131.953,143.002 131.953,143.891 132.715,144.653 U5.8@132.715,145.63
GPS_POWER_EN: R18.1 U4.43 | length 35.1
  Top Layer w0.5: v1(92.583,158.496) 90.551,156.464 90.551,142.24 92.964,139.827 v1(92.964,133.35)
  Bottom Layer w0.2: v1(92.964,133.35) 92.964,133.731 94.127,134.894 U4.43
  Bottom Layer w0.5: v1(92.583,158.496) 96.663,158.496 R18.1
GPS_RXD: P4.1 U4.36 U5.20 | length 35.4
  Top Layer w0.5: v1(101.092,128.651) 102.362,127.381 v1(104.648,127.381)
  Bottom Layer w0.2: U4.36 99.589,130.154 v1(101.092,128.651)
  Bottom Layer w0.5: v1(104.648,127.381) 104.775,127.508 125.095,127.508 126.365,128.778 P4.1 126.365,130.683 127.515,131.833 U5.20
GPS_TXD: P4.2 U4.35 U5.21 | length 31.8
  Top Layer w0.5: v1(102.108,129.032) 102.855,128.285 v1(105.029,128.285)
  Bottom Layer w0.2: U4.35 100.089,130.543 100.584,130.048 101.092,130.048 v1(102.108,129.032)
  Bottom Layer w0.5: v1(105.029,128.285) 105.156,128.158 122.062,128.158 P4.2 123.825,130.429 125.038,131.642 ; 125.163,131.767 125.038,131.642 ; U5.21 126.415,132.638 125.73,131.953 125.349,131.953 125.038,131.642
LOW_POWER_EN: U4.41 U7.4 U8.4 | length 51.5
  Top Layer w0.2: 93.98,133.731 94.099,133.612
  Top Layer w0.5: v1(94.996,132.715) 94.099,133.612 94.099,145.915 101.981,153.797 112.903,153.797 v1(113.538,154.432) ; v1(115.824,154.305) 116.874,155.355 U7.4 116.963,157.252 117.729,158.018 v1(117.729,158.115) ; U8.4 117.195,163.983 v1(117.856,163.322)
  Bottom Layer w0.2: v1(94.996,132.715) 94.996,132.842 95.664,133.51 U4.41
  Bottom Layer w0.5: v1(113.538,154.432) 115.697,154.432 v1(115.824,154.305) ; v1(117.729,158.115) 117.794,158.18 117.794,163.26 v1(117.856,163.322)
MG323_RESET: R4.1 U4.45 | length 87.1
  Top Layer w0.2: v1(58.293,138.176) 58.293,158.369 60.706,160.782 64.135,160.782 65.151,159.766 R4.1
  Bottom Layer w0.2: v1(58.293,138.176) 58.293,130.175 62.484,125.984 88.9,125.984 91.44,128.524 91.44,133.35 93.984,135.894 U4.45
MG323_TERM_ON: R6.1 U4.44 | length 68.3
  Top Layer w0.5: R6.1 63.119,147.955 60.833,145.669 60.833,139.7 58.166,137.033 58.166,129.794 61.722,126.238 90.043,126.238 v1(90.17,126.365)
  Bottom Layer w0.2: v1(90.17,126.365) 92.329,128.524 92.329,133.731 93.992,135.394 U4.44
NetC6_1: C6.1 Q2.3 U1.67 | length 9
  Top Layer w0.5: v1(60.452,153.289) 60.579,153.162 C6.1 ; v1(64.643,154.432) 64.654,154.421 Q2.3
  Bottom Layer w0.5: v1(60.452,153.289) 60.452,153.924 61.654,155.126 U1.67 63.949,155.126 v1(64.643,154.432)
NetC7_1: C7.1 Q3.3 U1.68 | length 12.2
  Top Layer w0.5: v1(59.309,156.21) 59.436,156.337 C7.1 61.341,156.337 65.14,152.538 Q3.3
  Bottom Layer w0.5: v1(59.309,156.21) 59.482,156.383 U1.68
NetC11_1: C11.1 D1.1 R11.2 R13.1 U2.5 | length 26
  Top Layer w0.5: v1(128.971,153.101) 130.053,152.019 U2.5 132.969,152.019 133.858,152.908 133.858,160.401 135.045,161.588 R11.2 ; v1(135.382,165.354) 135.382,164.04 R11.2 ; R13.1 R11.2
  Bottom Layer w0.5: C11.1 v1(128.971,153.101) ; D1.1 134.484,165.354 v1(135.382,165.354)
NetC11_2: C11.2 D1.2 R8.2 R10.1 U2.3 | length 22.9
  Top Layer w0.5: R8.2 R10.1 ; U2.3 125.984,153.289 126.917,154.222 v1@126.917,154.305 ; v1@126.917,154.432 R10.1 ; v1@127,154.305 v1(127,154.432) ; v1(127.127,165.735) 127.127,163.913 R10.1
  Bottom Layer w0.5: C11.2 127,152.588 v1(127,154.432) ; v1(127.127,165.735) 127.351,165.735 D1.2
NetC13_2: C13.2 R14.2 R15.1 U3.3 | length 11.7
  Top Layer w0.5: U3.3 138.176,153.289 138.811,153.924 v1(138.811,155.448)
  Bottom Layer w0.5: R15.1 136.42,154.051 C13.2 ; v1(138.811,155.448) 139.087,155.172 C13.2 ; R14.2 C13.2
NetC18_1: C18.1 U4.20 | length 8
  Top Layer w0.2: v1(109.855,131.318) 110.236,130.937 113.094,130.937 C18.1
  Bottom Layer w0.2: U4.20 109.014,132.159 v1(109.855,131.318)
NetC24_2: C24.2 U9.4 | length 3.5
  Top Layer w0.5: U9.4 101.459,163.59 v1(102.235,162.814)
  Bottom Layer w0.5: C24.2 101.537,162.814 v1(102.235,162.814)
NetD2_1: D2.1 R5.1 | length 11.8
  Top Layer w0.5: D2.1 126.619,139.446 127.635,138.43 133.604,138.43 134.62,139.446 R5.1
NetD2_2: D2.2 U5.3 | length 5.3
  Top Layer w0.5: D2.2 124.079,142.875 v1(124.714,143.51)
  Bottom Layer w0.5: v1(124.714,143.51) 125.315,144.111 U5.3
NetJ2_1: J2.1 TVS1.2 U1.4 | length 19.7
  Top Layer w0.5: J2.1 77.938,166.33 TVS1.2
  Bottom Layer w0.5: U1.4 68.645,160.336 67.183,161.798 67.183,165.481 68.032,166.33 J2.1
NetJ3_1: J3.1 TVS2.2 U5.11 | length 24.1
  Top Layer w0.5: TVS2.2 133.985,132.588 138.049,136.652 v1(138.049,142.748)
  Bottom Layer w0.5: U5.11 136.015,144.274 137.501,142.788 v1@138.049,142.788 ; v1(138.049,142.748) v1@138.049,142.788 ; 143.931,142.788 v1@138.049,142.788
NetP1_1: P1.1 R8.1 | length 10.7
  Top Layer w0.5: R8.1 121.412,164.465 123.698,166.751 126.746,166.751 128.822,168.827 P1.1
NetP2_1: P2.1 R13.2 | length 11.5
  Top Layer w0.5: P2.1 135.045,166.751 138.938,166.751 140.506,165.183 R13.2
NetQ1_1: Q1.1 Q4.3 R3.2 | length 6.9
  Top Layer w0.5: Q4.3 98.708,158.848 ; v1(98.933,158.623) 100.119,157.437 Q1.1
  Bottom Layer w0.5: v1(98.933,158.623) 98.933,158.56 R3.2
NetQ2_1: Q2.1 R4.2 | length 3
  Top Layer w0.5: Q2.1 68.718,156.221 R4.2
NetQ3_1: Q3.1 R6.2 | length 8.5
  Top Layer w0.2: Q3.1 65.99,151.511 66.421,151.511 67.056,152.146 68.072,152.146 v1(68.453,151.765) ; R6.2 69.088,149.098 v1(69.088,149.352)
  Bottom Layer w0.2: v1(68.453,151.765) 68.453,149.987 v1(69.088,149.352)
NetQ4_1: Q4.1 R18.2 | length 2.7
  Top Layer w0.5: v1(95.25,156.464) Q4.1@95.834,157.048
  Bottom Layer w0.5: v1(95.25,156.464) 95.417,156.297 R18.2
NetQ5_1: Q5.1 Q6.3 R16.2 | length 12.5
  Top Layer w0.5: Q5.1 104.233,156.464 v1(104.013,156.464) 104.648,155.829 108.331,155.829 109.093,156.591 109.093,157.988 109.953,158.848 Q6.3
  Bottom Layer w0.5: v1(104.013,156.464) 104.053,156.424 R16.2
NetQ6_1: Q6.1 R17.2 | length 3.3
  Top Layer w0.5: Q6.1 111.125,156.202 v1(111.125,155.321)
  Bottom Layer w0.5: R17.2 111.125,156.528 v1(111.125,155.321)
NetR1_1: R1.1 U1.42 | length 5.4
  Bottom Layer w0.5: R1.1 76.187,129.146 U1.42
NetR9_1: R9.1 U2.1 U2.2 | length 14.5
  Top Layer w0.5: v1(118.237,147.066) 118.618,147.447 118.618,151.765 121.412,154.559 U2.2 U2.1
  Bottom Layer w0.5: R9.1 118.07,146.899 v1(118.237,147.066)
NetR12_1: R12.1 U2.6 U2.7 | length 22.9
  Top Layer w0.5: v1(129.921,153.924) 131.024,153.924 U2.6 U2.7
  Bottom Layer w0.5: R12.1 130.008,149.566 131.699,151.257 131.699,153.162 130.937,153.924 v1(129.921,153.924)
NetS1_1: S1.1 U4.46 | length 8.2
  Top Layer w0.2: S1.1 97.409,132.905 v1(97.409,133.858)
  Bottom Layer w0.2: U4.46 97.159,136.394 97.409,136.144 v1(97.409,133.858)
NetU4_21: U4.21 Y1.2 | length 2.7
  Bottom Layer w0.2: U4.21@107.089,131.699 108.442,130.346 Y1.2
NetU4_22: U4.22 Y1.1 | length 2.5
  Bottom Layer w0.2: Y1.1 106.589,129.687 U4.22
PERIPHERAL_POWER_EN: R17.1 U4.42 U9.3 | length 57.6
  Top Layer w0.2: v1(93.599,132.588) 93.599,140.208 91.186,142.621 91.186,155.702 93.345,157.861 93.345,161.798 95.657,164.11 U9.3
  Top Layer w0.5: v1(104.775,161.163) 105.791,162.179 v1(106.426,162.179)
  Bottom Layer w0.2: v1(93.599,132.588) 93.599,133.604 94.389,134.394 U4.42
  Bottom Layer w0.5: v1(98.298,164.084) 98.298,163.83 100.203,161.925 104.013,161.925 v1(104.775,161.163) ; v1(106.426,162.179) 106.426,162.306 107.887,162.306 R17.1
RST: C14.2 P5.3 R2.2 U4.80 | length 14.7
  Top Layer w0.5: P5.3 105.664,146.749 ; R2.2 105.664,146.749 ; C14.2 108.649,146.749 105.664,146.749
  Bottom Layer w0.2: P5.3 105.601,146.812 106.807,146.812 107.089,146.53 U4.80
SIM_CLK: C3.1 J1.3 U1.55 | length 16.8
  Top Layer w0.5: v1(64.516,140.081) 65.151,140.081 67.691,142.621 ; J1.3 67.691,138.526 67.691,142.621 ; C3.1 67.691,144.907 67.691,142.621
  Bottom Layer w0.5: U1.55 64.477,140.042 v1(64.516,140.081)
SIM_DATA: C2.1 J1.4 U1.56 | length 33
  Top Layer w0.5: v1(69.977,141.097) 78.227,141.097 v1@82.547,136.776 ; v1(82.55,136.779) v1@82.547,136.776 ; J1.4 v1@82.547,136.776
  Bottom Layer w0.5: U1.56 69.775,141.299 v1(69.977,141.097) ; v1(82.55,136.779) 84.836,136.779 86.487,135.128 86.487,133.731 85.852,133.096 85.344,133.096 C2.1
SIM_RST: C1.1 J1.2 U1.57 | length 31.2
  Top Layer w0.5: J1.2 70.383,132.994 72.136,134.747 ; v1(71.12,131.826) 72.136,132.842 72.136,134.747 ; v1(71.882,139.7) 72.136,139.446 72.136,134.747
  Bottom Layer w0.5: U1.57 71.185,142.556 71.882,141.859 v1(71.882,139.7) ; C1.1 70.104,130.683 71.12,131.699 v1(71.12,131.826)
TEST: P5.2 U4.75 | length 4.7
  Bottom Layer w0.2: P5.2 103.061,146.812 104.14,146.812 104.589,146.363 U4.75
TEST_RXD: P3.1 U4.13 | length 2.8
  Bottom Layer w0.2: U4.13 111.463,137.394 P3.1
TEST_TXD: P3.2 U4.14 | length 6.6
  Bottom Layer w0.2: U4.14 109.089,136.819 109.942,136.819 110.114,136.647 110.114,136.393 110.744,135.763 113.157,135.763 114.277,136.883 P3.2
V_BAT: BT1.2 Q1.2 Q5.2 R3.1 R16.1 U7.1 U7.3 U8.1 U8.3 U9.1 | length 58.5
  Top Layer w0.5: U9.1 100.657,167.259 108.014,167.259 109.959,165.314 111.038,165.314 ; v1(103.505,158.877) 103.505,158.535 Q1.2 102.439,157.048 104.801,154.686 109.728,154.686 109.793,154.621 112.203,154.621 112.903,155.321 112.903,156.236 113.919,157.252 113.639,157.252 113.127,157.764 113.127,160.498 ; Q5.2 106.921,157.099 v1(107.696,157.099) ; v1(111.633,161.163) 112.463,161.163 113.127,160.498 ; U7.1 113.127,160.498 ; U8.3 112.369,163.983 111.038,165.314 ; U8.1 112.289,165.883 111.72,165.314 111.038,165.314
  Bottom Layer w0.5: R3.1 R16.1 106.085,158.964 107.696,157.353 v1(107.696,157.099) ; BT1.2@109.959,165.314 109.959,162.837 v1(111.633,161.163)
V_OFFSET: R10.2 R11.1 U3.1 U3.2 | length 13.8
  Top Layer w0.5: R10.2 R11.1 132.505,162.135 v1(133.223,161.417) ; U3.2 136.144,154.685 v1(136.144,157.353)
  Bottom Layer w0.5: v1(133.223,161.417) 136.144,158.496 v1(136.144,157.353)
VSIM: C4.1 J1.1 U1.58 | length 35.1
  Top Layer w0.5: J1.1 J1.1@65.253,130.454 ; v1(66.548,128.016) 66.548,129.159 J1.1@65.253,130.454 ; v1(74.041,139.827) 74.041,132.842 71.653,130.454 J1.1@65.253,130.454
  Bottom Layer w0.5: U1.58 71.706,143.813 74.041,141.478 v1(74.041,139.827) ; C4.1 66.294,128.27 v1(66.548,128.016)
pads on no net: J1.5 U1.10 U1.11 U1.12 U1.13 U1.14 U1.15 U1.16 U1.17 U1.18 U1.19 U1.20 U1.24 U1.25 U1.26 U1.27 U1.30 U1.31 U1.33 U1.34 U1.35 U1.36 U1.37 U1.38 U1.39 U1.40 U1.44 U1.46 U1.47 U1.48 U1.49 U1.50 U1.51 U1.52 U1.53 U1.59 U1.61 U1.62 U1.63 U1.64 U1.66 U3.5 U3.6 U3.7 U4.11 U4.12 U4.26 U4.27 U4.28 U4.29 U4.30 U4.31 U4.32 U4.33 U4.34 U4.37 U4.38 U4.39 U4.40 U4.47 U4.48 U4.49 U4.50 U4.51 U4.52 U4.53 U4.54 U4.55 U4.56 U4.57 U4.58 U4.61 U4.62 U4.63 U4.64 U4.65 U4.66 U4.67 U4.68 U4.69 U4.70 U4.71 U4.72 U4.73 U4.74 U4.76 U4.77 U4.78 U4.79 U5.1 U5.2 U5.4 U5.5 U5.6 U5.9 U5.14 U5.15 U5.16 U5.17 U5.18 U5.19

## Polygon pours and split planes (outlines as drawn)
no net on Internal Plane 1 (split plane): 148.99,122.303 52.61,122.303 52.61,174.39 148.99,174.39
no net on Internal Plane 2 (split plane): 148.99,122.303 52.61,122.303 52.61,174.39 148.99,174.39

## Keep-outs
Keep-Out Layer:
  the board outline again, w0.3

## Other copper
Top Layer:
  pour cut-out: 99.314,135.509 118.745,135.509 119.253,136.017 119.253,154.94 99.441,154.94 99.314,155.067
  pour cut-out: 119.761,172.593 119.761,147.955 146.939,147.955 146.939,164.084 138.557,172.466
Bottom Layer:
  pour cut-out: 100.33,146.431 99.822,145.923 99.822,135.509 118.364,135.509 118.618,135.255 119.38,136.017 119.38,146.431
  pour cut-out: 119.634,172.847 119.634,147.828 147.447,147.828 147.193,148.082 147.193,164.211 138.684,172.72

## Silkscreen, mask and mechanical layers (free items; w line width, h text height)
Top Overlay:
  text "+" at 125.52,168.783 h1.52
  text "-" at 134.664,168.656 h1.52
